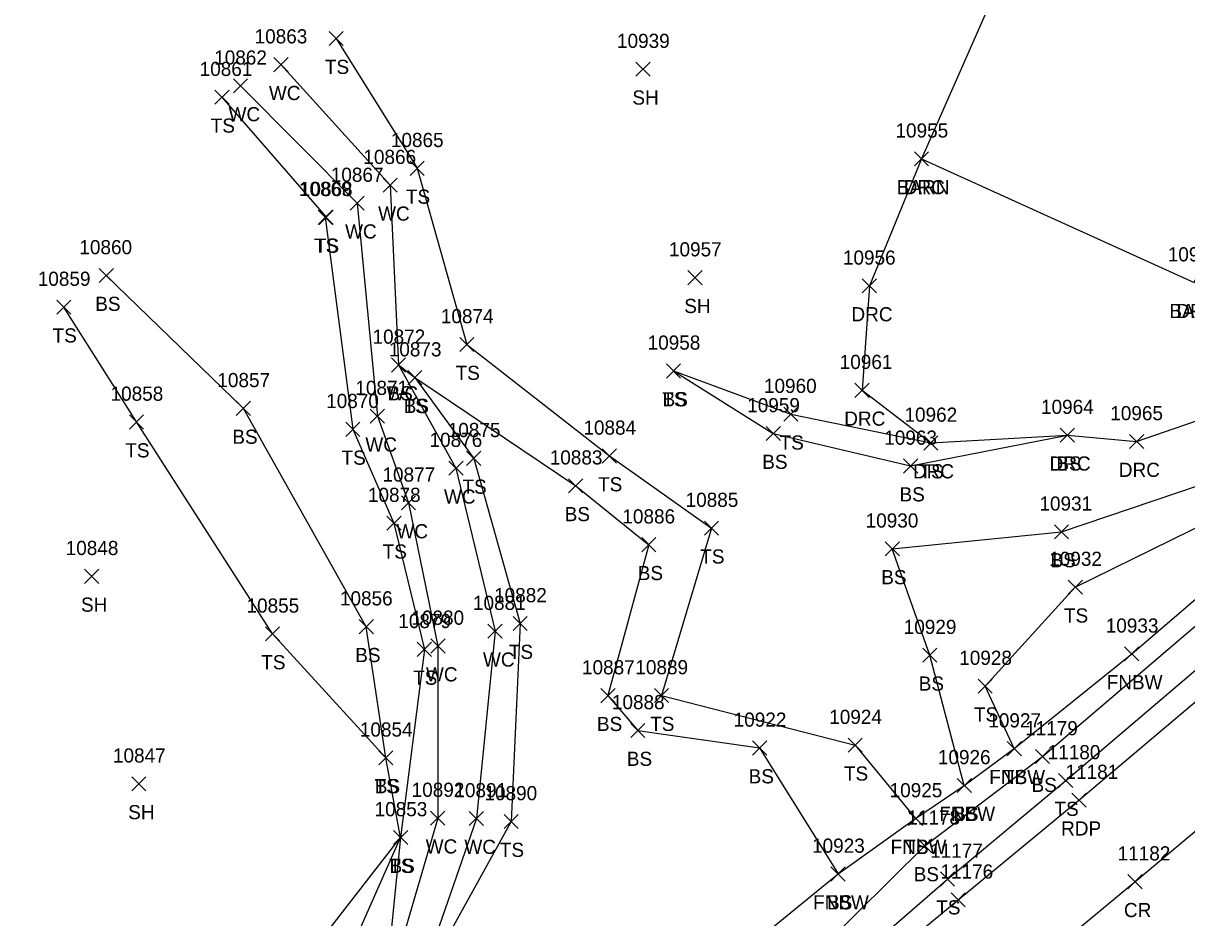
# Model space of a CAD drawing. Extents: x 1475671 to 1477951, y 592661 to 593821.
# Drawn here: x 1476576.7 to 1476740.9, y 593233.2 to 593359.5 of the extents above; entities that cross this region are included whole.
import ezdxf

# ---------------------------------------------------------------- set-up
doc = ezdxf.new("R2010")
doc.units = 0
for name, color, linetype in [('L_A', 7, 'Continuous'), ('L_I', 7, 'Continuous'), ('L_TIC', 7, 'Continuous'), ('LAWE', 7, 'Continuous'), ('LBC', 7, 'Continuous'), ('LELB', 7, 'Continuous'), ('LFNC', 7, 'Continuous'), ('P_A', 7, 'Continuous'), ('P_I', 7, 'Continuous'), ('P_TIC', 7, 'Continuous'), ('PET', 7, 'Continuous'), ('PRC', 7, 'Continuous'), ('R_A', 7, 'Continuous'), ('R_I', 7, 'Continuous'), ('R_TIC', 7, 'Continuous'), ('RDP', 7, 'Continuous')]:
    doc.layers.add(name, color=color, linetype=linetype)

msp = doc.modelspace()

# ---------------------------------------------------------------- linework, layer by layer
at = {"layer": 'L_TIC'}
for points in [[(1476619.88, 593356.33), (1476621.88, 593358.33)], [(1476621.88, 593356.33), (1476619.88, 593358.33)], [(1476612.09, 593352.64), (1476614.09, 593354.64)], [(1476614.09, 593352.64), (1476612.09, 593354.64)], [(1476663.18, 593352), (1476665.18, 593354)], [(1476665.18, 593352), (1476663.18, 593354)], [(1476606.39, 593349.65), (1476608.39, 593351.65)], [(1476608.39, 593349.65), (1476606.39, 593351.65)], [(1476603.77, 593348.04), (1476605.77, 593350.04)], [(1476605.77, 593348.04), (1476603.77, 593350.04)], [(1476631.31, 593338.01), (1476633.31, 593340.01)], [(1476633.31, 593338.01), (1476631.31, 593340.01)], [(1476702.46, 593339.35), (1476704.46, 593341.35)], [(1476704.46, 593339.35), (1476702.46, 593341.35)], [(1476627.49, 593335.62), (1476629.49, 593337.62)], [(1476629.49, 593335.62), (1476627.49, 593337.62)], [(1476622.84, 593333.1), (1476624.84, 593335.1)], [(1476624.84, 593333.1), (1476622.84, 593335.1)], [(1476618.35, 593331.1), (1476620.35, 593333.1)], [(1476620.35, 593331.1), (1476618.35, 593333.1)], [(1476618.47, 593331.09), (1476620.47, 593333.09)], [(1476620.47, 593331.09), (1476618.47, 593333.09)], [(1476587.45, 593322.88), (1476589.45, 593324.88)], [(1476589.45, 593322.88), (1476587.45, 593324.88)], [(1476670.5, 593322.58), (1476672.5, 593324.58)], [(1476672.5, 593322.58), (1476670.5, 593324.58)], [(1476581.46, 593318.42), (1476583.46, 593320.42)], [(1476583.46, 593318.42), (1476581.46, 593320.42)], [(1476638.32, 593313.14), (1476640.32, 593315.14)], [(1476640.32, 593313.14), (1476638.32, 593315.14)], [(1476628.68, 593310.25), (1476630.68, 593312.25)], [(1476630.68, 593310.25), (1476628.68, 593312.25)], [(1476628.68, 593310.25), (1476630.68, 593312.25)], [(1476630.68, 593310.25), (1476628.68, 593312.25)], [(1476630.97, 593308.46), (1476632.97, 593310.46)], [(1476632.97, 593308.46), (1476630.97, 593310.46)], [(1476630.97, 593308.46), (1476632.97, 593310.46)], [(1476632.97, 593308.46), (1476630.97, 593310.46)], [(1476667.48, 593309.41), (1476669.48, 593311.41)], [(1476669.48, 593309.41), (1476667.48, 593311.41)], [(1476667.48, 593309.41), (1476669.48, 593311.41)], [(1476669.48, 593309.41), (1476667.48, 593311.41)], [(1476606.79, 593304.12), (1476608.79, 593306.12)], [(1476608.79, 593304.12), (1476606.79, 593306.12)], [(1476591.72, 593302.2), (1476593.72, 593304.2)], [(1476593.72, 593302.2), (1476591.72, 593304.2)], [(1476625.69, 593303.02), (1476627.69, 593305.02)], [(1476627.69, 593303.02), (1476625.69, 593305.02)], [(1476684.03, 593303.3), (1476686.03, 593305.3)], [(1476686.03, 593303.3), (1476684.03, 593305.3)], [(1476622.23, 593301.17), (1476624.23, 593303.17)], [(1476624.23, 593301.17), (1476622.23, 593303.17)], [(1476681.55, 593300.58), (1476683.55, 593302.58)], [(1476683.55, 593300.58), (1476681.55, 593302.58)], [(1476723.04, 593300.34), (1476725.04, 593302.34)], [(1476725.04, 593300.34), (1476723.04, 593302.34)], [(1476703.77, 593299.24), (1476705.77, 593301.24)], [(1476705.77, 593299.24), (1476703.77, 593301.24)], [(1476639.29, 593297.07), (1476641.29, 593299.07)], [(1476641.29, 593297.07), (1476639.29, 593299.07)], [(1476658.42, 593297.41), (1476660.42, 593299.41)], [(1476660.42, 593297.41), (1476658.42, 593299.41)], [(1476636.78, 593295.68), (1476638.78, 593297.68)], [(1476638.78, 593295.68), (1476636.78, 593297.68)], [(1476700.92, 593295.99), (1476702.92, 593297.99)], [(1476702.92, 593295.99), (1476700.92, 593297.99)], [(1476653.68, 593293.2), (1476655.68, 593295.2)], [(1476655.68, 593293.2), (1476653.68, 593295.2)], [(1476630.08, 593290.78), (1476632.08, 593292.78)], [(1476632.08, 593290.78), (1476630.08, 593292.78)], [(1476628.03, 593287.92), (1476630.03, 593289.92)], [(1476630.03, 593287.92), (1476628.03, 593289.92)], [(1476672.84, 593287.22), (1476674.84, 593289.22)], [(1476674.84, 593287.22), (1476672.84, 593289.22)], [(1476722.21, 593286.69), (1476724.21, 593288.69)], [(1476724.21, 593286.69), (1476722.21, 593288.69)], [(1476663.99, 593284.88), (1476665.99, 593286.88)], [(1476665.99, 593284.88), (1476663.99, 593286.88)], [(1476698.34, 593284.3), (1476700.34, 593286.3)], [(1476700.34, 593284.3), (1476698.34, 593286.3)], [(1476585.39, 593280.42), (1476587.39, 593282.42)], [(1476587.39, 593280.42), (1476585.39, 593282.42)], [(1476724.15, 593278.89), (1476726.15, 593280.89)], [(1476726.15, 593278.89), (1476724.15, 593280.89)], [(1476645.83, 593273.76), (1476647.83, 593275.76)], [(1476647.83, 593273.76), (1476645.83, 593275.76)], [(1476610.9, 593272.29), (1476612.9, 593274.29)], [(1476612.9, 593272.29), (1476610.9, 593274.29)], [(1476624.13, 593273.31), (1476626.13, 593275.31)], [(1476626.13, 593273.31), (1476624.13, 593275.31)], [(1476642.29, 593272.67), (1476644.29, 593274.67)], [(1476644.29, 593272.67), (1476642.29, 593274.67)], [(1476634.24, 593270.58), (1476636.24, 593272.58)], [(1476636.24, 593270.58), (1476634.24, 593272.58)], [(1476632.33, 593270.11), (1476634.33, 593272.11)], [(1476634.33, 593270.11), (1476632.33, 593272.11)], [(1476703.63, 593269.28), (1476705.63, 593271.28)], [(1476705.63, 593269.28), (1476703.63, 593271.28)], [(1476732.12, 593269.47), (1476734.12, 593271.47)], [(1476734.12, 593269.47), (1476732.12, 593271.47)], [(1476711.45, 593264.92), (1476713.45, 593266.92)], [(1476713.45, 593264.92), (1476711.45, 593266.92)], [(1476658.23, 593263.58), (1476660.23, 593265.58)], [(1476660.23, 593263.58), (1476658.23, 593265.58)], [(1476665.77, 593263.59), (1476667.77, 593265.59)], [(1476667.77, 593263.59), (1476665.77, 593265.59)], [(1476662.45, 593258.66), (1476664.45, 593260.66)], [(1476664.45, 593258.66), (1476662.45, 593260.66)], [(1476679.62, 593256.19), (1476681.62, 593258.19)], [(1476681.62, 593256.19), (1476679.62, 593258.19)], [(1476693.11, 593256.58), (1476695.11, 593258.58)], [(1476695.11, 593256.58), (1476693.11, 593258.58)], [(1476715.55, 593256.09), (1476717.55, 593258.09)], [(1476717.55, 593256.09), (1476715.55, 593258.09)], [(1476715.55, 593256.09), (1476717.55, 593258.09)], [(1476717.55, 593256.09), (1476715.55, 593258.09)], [(1476626.89, 593254.79), (1476628.89, 593256.79)], [(1476628.89, 593254.79), (1476626.89, 593256.79)], [(1476626.89, 593254.79), (1476628.89, 593256.79)], [(1476628.89, 593254.79), (1476626.89, 593256.79)], [(1476719.54, 593254.98), (1476721.54, 593256.98)], [(1476721.54, 593254.98), (1476719.54, 593256.98)], [(1476592.05, 593251.13), (1476594.05, 593253.13)], [(1476594.05, 593251.13), (1476592.05, 593253.13)], [(1476708.5, 593250.9), (1476710.5, 593252.9)], [(1476710.5, 593250.9), (1476708.5, 593252.9)], [(1476708.5, 593250.9), (1476710.5, 593252.9)], [(1476710.5, 593250.9), (1476708.5, 593252.9)], [(1476722.81, 593251.6), (1476724.81, 593253.6)], [(1476724.81, 593251.6), (1476722.81, 593253.6)], [(1476634.2, 593246.29), (1476636.2, 593248.29)], [(1476636.2, 593246.29), (1476634.2, 593248.29)], [(1476639.66, 593246.23), (1476641.66, 593248.23)], [(1476641.66, 593246.23), (1476639.66, 593248.23)], [(1476701.63, 593246.23), (1476703.63, 593248.23)], [(1476703.63, 593246.23), (1476701.63, 593248.23)], [(1476701.63, 593246.23), (1476703.63, 593248.23)], [(1476703.63, 593246.23), (1476701.63, 593248.23)], [(1476644.56, 593245.81), (1476646.56, 593247.81)], [(1476646.56, 593245.81), (1476644.56, 593247.81)], [(1476628.97, 593243.55), (1476630.97, 593245.55)], [(1476630.97, 593243.55), (1476628.97, 593245.55)], [(1476628.97, 593243.55), (1476630.97, 593245.55)], [(1476630.97, 593243.55), (1476628.97, 593245.55)], [(1476628.97, 593243.55), (1476630.97, 593245.55)], [(1476630.97, 593243.55), (1476628.97, 593245.55)], [(1476702.92, 593242.37), (1476704.92, 593244.37)], [(1476704.92, 593242.37), (1476702.92, 593244.37)], [(1476690.69, 593238.4), (1476692.69, 593240.4)], [(1476692.69, 593238.4), (1476690.69, 593240.4)], [(1476690.69, 593238.4), (1476692.69, 593240.4)], [(1476692.69, 593238.4), (1476690.69, 593240.4)], [(1476706.13, 593237.69), (1476708.13, 593239.69)], [(1476708.13, 593237.69), (1476706.13, 593239.69)]]:
    msp.add_lwpolyline(points, dxfattribs=at)
at = {"layer": 'LAWE'}
for points in [[(1476613.09, 593353.64), (1476628.49, 593336.62), (1476629.68, 593311.25), (1476637.78, 593296.68), (1476643.29, 593273.67), (1476640.66, 593247.23), (1476633.78, 593227.3), (1476632.16, 593210.64), (1476623.48, 593192.05), (1476621.73, 593187.97), (1476618.95, 593180.66)], [(1476607.39, 593350.65), (1476623.84, 593334.1), (1476626.69, 593304.02), (1476631.08, 593291.78), (1476635.24, 593271.58), (1476635.2, 593247.29), (1476629.57, 593228.01), (1476628.52, 593211.44), (1476620.49, 593193.84), (1476617.53, 593189.7), (1476607.49, 593183.62), (1476609.32, 593177.24), (1476612.65, 593176.23), (1476614.24, 593174.55), (1476618.55, 593176.15), (1476618.95, 593180.66)]]:
    msp.add_lwpolyline(points, dxfattribs=at)
at = {"layer": 'LBC'}
msp.add_lwpolyline([(1476766.99, 593478.72), (1476749.47, 593442.92), (1476737.05, 593415.38), (1476717.88, 593373.12), (1476703.46, 593340.35), (1476741.92, 593322.87), (1476753.1, 593346.5), (1476762.35, 593367.35), (1476787.68, 593423.01), (1476791.87, 593432.58)], dxfattribs=at)
at = {"layer": 'LELB'}
for points in [[(1476660.79, 593199.46), (1476674.63, 593214.33), (1476703.92, 593243.37), (1476720.54, 593255.98), (1476751.7, 593282.61), (1476781.77, 593307.79), (1476789.04, 593316.89), (1476807.89, 593333.24), (1476839.71, 593357.28), (1476859.97, 593374.46), (1476882.16, 593391.96), (1476882.87, 593395.08), (1476884.75, 593398.78), (1476886.94, 593401.06), (1476880.92, 593405.09), (1476872.21, 593402.61), (1476869.35, 593406.91), (1476883.46, 593416.6), (1476894.87, 593423.54), (1476922.16, 593439.01), (1476941.74, 593451.3), (1476958.3, 593465.19), (1476973.77, 593478.9)], [(1476525.71, 593116.6), (1476535.99, 593117.47), (1476564.39, 593135.96), (1476604.97, 593161.16), (1476624.83, 593173.86), (1476638.09, 593183.34), (1476660.79, 593199.46), (1476676.81, 593212.32), (1476707.13, 593238.69), (1476723.81, 593252.6), (1476754.14, 593278.44), (1476785.31, 593303.01), (1476812.8, 593326.19), (1476842.99, 593352.59), (1476863.07, 593369.43), (1476886.56, 593389.77), (1476893.66, 593396.85), (1476901.2, 593401.68), (1476921.17, 593422.2)], [(1476709.5, 593251.9), (1476704.63, 593270.28), (1476699.34, 593285.3), (1476723.21, 593287.69), (1476755.77, 593298.72), (1476777.04, 593314.27), (1476785.1, 593323.82), (1476803.07, 593341.35), (1476835.49, 593361.82), (1476853.06, 593384.39), (1476874.85, 593397.11), (1476884.75, 593398.78)], [(1476716.55, 593257.09), (1476712.45, 593265.92), (1476725.15, 593279.89), (1476757.78, 593295.95), (1476779.66, 593309.61), (1476787.04, 593319.52), (1476805.64, 593337.64), (1476837.49, 593359.29), (1476857.09, 593379.03), (1476877.34, 593393.41), (1476882.87, 593395.08)], [(1476620.88, 593357.33), (1476632.31, 593339.01), (1476639.32, 593314.14), (1476659.42, 593298.41), (1476673.84, 593288.22), (1476666.77, 593264.59), (1476694.11, 593257.58), (1476702.63, 593247.23)], [(1476604.77, 593349.04), (1476619.47, 593332.09), (1476619.35, 593332.1), (1476623.23, 593302.17), (1476629.03, 593288.92), (1476633.33, 593271.11)], [(1476627.89, 593255.79), (1476625.13, 593274.31), (1476607.79, 593305.12), (1476588.45, 593323.88)], [(1476629.97, 593244.55), (1476627.89, 593255.79), (1476611.9, 593273.29), (1476592.72, 593303.2), (1476582.46, 593319.42)], [(1476629.68, 593311.25), (1476631.97, 593309.46), (1476654.68, 593294.2), (1476664.99, 593285.88), (1476659.23, 593264.58), (1476663.45, 593259.66), (1476680.62, 593257.19), (1476691.69, 593239.4)], [(1476668.48, 593310.41), (1476685.03, 593304.3), (1476704.77, 593300.24)], [(1476668.48, 593310.41), (1476682.55, 593301.58), (1476701.92, 593296.99), (1476724.04, 593301.34)], [(1476631.97, 593309.46), (1476640.29, 593298.07), (1476646.83, 593274.76), (1476645.56, 593246.81), (1476635.23, 593228.07), (1476634.06, 593210.85), (1476624.18, 593191.42), (1476621.73, 593187.97), (1476617.53, 593189.7)], [(1476633.33, 593271.11), (1476629.97, 593244.55)], [(1476600.34, 593167.51), (1476594.26, 593178.25), (1476596.2, 593189.62), (1476609.35, 593213.75), (1476616.22, 593226.87), (1476629.97, 593244.55), (1476628.33, 593228.14), (1476627.49, 593211.59), (1476619.26, 593195.1), (1476617.53, 593189.7)], [(1476602.47, 593173.82), (1476600.14, 593185.69), (1476613.85, 593211.55), (1476621.5, 593225.4), (1476629.97, 593244.55)]]:
    msp.add_lwpolyline(points, dxfattribs=at)
at = {"layer": 'LFNC'}
msp.add_lwpolyline([(1476458.99, 593083.01), (1476499.73, 593099.84), (1476506.4, 593103.47), (1476506.74, 593103.7), (1476516.66, 593109.69), (1476525.71, 593116.6), (1476534.13, 593120.72), (1476545.43, 593126.64), (1476563.76, 593138.28), (1476600.34, 593167.51), (1476610.45, 593174.4), (1476612.65, 593176.23), (1476618.95, 593180.66), (1476640, 593195.61), (1476653.4, 593207.77), (1476664.49, 593217.17), (1476691.69, 593239.4), (1476702.63, 593247.23), (1476709.5, 593251.9), (1476716.55, 593257.09), (1476733.12, 593270.47), (1476759.81, 593293.37)], dxfattribs=at)
at = {"layer": 'P_TIC'}
for points in [[(1476724.67, 593248.83), (1476726.67, 593250.83)], [(1476726.67, 593248.83), (1476724.67, 593250.83)], [(1476732.58, 593237.31), (1476734.58, 593239.31)], [(1476734.58, 593237.31), (1476732.58, 593239.31)], [(1476707.64, 593234.75), (1476709.64, 593236.75)], [(1476709.64, 593234.75), (1476707.64, 593236.75)]]:
    msp.add_lwpolyline(points, dxfattribs=at)
at = {"layer": 'PET'}
msp.add_lwpolyline([(1476459.25, 593078.48), (1476508.39, 593100.17), (1476518.15, 593105.13), (1476565.38, 593131.07), (1476607.43, 593157.45), (1476640.25, 593180.54), (1476678.21, 593210.57), (1476708.64, 593235.75), (1476725.67, 593249.83), (1476755.84, 593275.3), (1476786.3, 593300.73), (1476814.32, 593324.28), (1476845.05, 593350.02), (1476865.02, 593366.82), (1476897.04, 593395.14), (1476922.98, 593419.08), (1476952.36, 593443.37)], dxfattribs=at)
at = {"layer": 'PRC'}
msp.add_lwpolyline([(1476461.98, 593064.62), (1476520.7, 593090.52), (1476540.79, 593101.34), (1476577.67, 593121.61), (1476614.51, 593145.69), (1476649.36, 593170.81), (1476687.02, 593200.01), (1476716.69, 593224.25), (1476733.58, 593238.31), (1476760.9, 593261.21), (1476795.35, 593290.14), (1476823.06, 593313.51), (1476854.07, 593339.52), (1476875.7, 593357.51), (1476907.01, 593384.08), (1476934.06, 593407.68), (1476963.46, 593432.81)], dxfattribs=at)
at = {"layer": 'R_TIC'}
for points in [[(1476702.46, 593339.35), (1476704.46, 593341.35)], [(1476704.46, 593339.35), (1476702.46, 593341.35)], [(1476695.1, 593321.41), (1476697.1, 593323.41)], [(1476697.1, 593321.41), (1476695.1, 593323.41)], [(1476694.07, 593306.68), (1476696.07, 593308.68)], [(1476696.07, 593306.68), (1476694.07, 593308.68)], [(1476723.04, 593300.34), (1476725.04, 593302.34)], [(1476725.04, 593300.34), (1476723.04, 593302.34)], [(1476703.77, 593299.24), (1476705.77, 593301.24)], [(1476705.77, 593299.24), (1476703.77, 593301.24)], [(1476732.81, 593299.45), (1476734.81, 593301.45)], [(1476734.81, 593299.45), (1476732.81, 593301.45)]]:
    msp.add_lwpolyline(points, dxfattribs=at)
at = {"layer": 'RDP'}
msp.add_lwpolyline([(1476703.46, 593340.35), (1476696.1, 593322.41), (1476695.07, 593307.68), (1476704.77, 593300.24), (1476724.04, 593301.34), (1476733.81, 593300.45), (1476747.14, 593305.07), (1476767.96, 593315.71), (1476784.22, 593330.11), (1476798.42, 593350.68), (1476808.5, 593366.53)], dxfattribs=at)

# ---------------------------------------------------------------- texts
at = {"layer": 'L_A'}
for s, p in [('TS', (1476619.29, 593352.33)), ('WC', (1476611.39, 593348.64)), ('SH', (1476662.67, 593348)), ('WC', (1476605.7, 593345.65)), ('TS', (1476603.18, 593344.04)), ('BARN', (1476699.97, 593335.35)), ('TS', (1476630.72, 593334.01)), ('WC', (1476626.8, 593331.62)), ('WC', (1476622.14, 593329.1)), ('TS', (1476617.76, 593327.1)), ('TS', (1476617.88, 593327.09)), ('BS', (1476586.89, 593318.88)), ('SH', (1476669.99, 593318.58)), ('BARN', (1476738.43, 593317.87)), ('TS', (1476580.87, 593314.42)), ('TS', (1476637.73, 593309.14)), ('WC', (1476627.99, 593306.25)), ('BS', (1476628.12, 593306.25)), ('TS', (1476666.89, 593305.41)), ('BS', (1476666.93, 593305.41)), ('TS', (1476630.38, 593304.46)), ('BS', (1476630.41, 593304.46)), ('BS', (1476606.23, 593300.12)), ('WC', (1476625, 593299.02)), ('TS', (1476683.44, 593299.3)), ('TS', (1476591.13, 593298.2)), ('TS', (1476621.64, 593297.17)), ('BS', (1476680.99, 593296.58)), ('TS', (1476703.18, 593295.24)), ('BS', (1476722.48, 593296.34)), ('TS', (1476638.7, 593293.07)), ('TS', (1476657.83, 593293.41)), ('BS', (1476700.36, 593291.99)), ('WC', (1476636.09, 593291.68)), ('BS', (1476653.12, 593289.2)), ('WC', (1476629.39, 593286.78)), ('TS', (1476627.44, 593283.92)), ('TS', (1476672.25, 593283.22)), ('BS', (1476721.65, 593282.69)), ('BS', (1476663.43, 593280.88)), ('BS', (1476697.78, 593280.3)), ('SH', (1476584.88, 593276.42)), ('TS', (1476723.56, 593274.89)), ('BS', (1476623.57, 593269.31)), ('TS', (1476645.24, 593269.76)), ('TS', (1476610.31, 593268.29)), ('WC', (1476641.59, 593268.67)), ('TS', (1476631.74, 593266.11)), ('WC', (1476633.55, 593266.58)), ('BS', (1476703.07, 593265.28)), ('FNBW', (1476729.59, 593265.47)), ('TS', (1476710.86, 593260.92)), ('BS', (1476657.67, 593259.58)), ('TS', (1476665.18, 593259.59)), ('BS', (1476661.89, 593254.66)), ('TS', (1476692.52, 593252.58)), ('TS', (1476626.3, 593250.79)), ('BS', (1476626.33, 593250.79)), ('BS', (1476679.07, 593252.19)), ('FNBW', (1476713.02, 593252.09)), ('TS', (1476714.96, 593252.09)), ('BS', (1476718.98, 593250.98)), ('TS', (1476722.22, 593247.6)), ('SH', (1476591.54, 593247.13)), ('FNBW', (1476705.97, 593246.9)), ('BS', (1476707.94, 593246.9)), ('WC', (1476633.51, 593242.29)), ('WC', (1476638.97, 593242.23)), ('TS', (1476643.97, 593241.81)), ('FNBW', (1476699.1, 593242.23)), ('TS', (1476701.04, 593242.23)), ('TS', (1476628.38, 593239.55)), ('TS', (1476628.38, 593239.55)), ('BS', (1476628.41, 593239.55)), ('BS', (1476702.36, 593238.37)), ('FNBW', (1476688.16, 593234.4)), ('BS', (1476690.13, 593234.4)), ('TS', (1476705.54, 593233.69))]:
    msp.add_text(s, height=2, dxfattribs=at).set_placement(p)
at = {"layer": 'L_I'}
for s, p in [('10863', (1476609.37, 593356.64)), ('10939', (1476660.5, 593356)), ('10862', (1476603.67, 593353.65)), ('10861', (1476601.62, 593352.04)), ('10955', (1476699.79, 593343.35)), ('10865', (1476628.6, 593342.01)), ('10866', (1476624.72, 593339.62)), ('10867', (1476620.12, 593337.1)), ('10869', (1476615.63, 593335.1)), ('10868', (1476615.76, 593335.09)), ('10860', (1476584.65, 593326.88)), ('10957', (1476667.83, 593326.58)), ('10967', (1476738.2, 593325.87)), ('10859', (1476578.78, 593322.42)), ('10874', (1476635.65, 593317.14)), ('10872', (1476626.01, 593314.25)), ('10872', (1476626.01, 593314.25)), ('10958', (1476664.82, 593313.41)), ('10958', (1476664.82, 593313.41)), ('10873', (1476628.3, 593312.46)), ('10873', (1476628.3, 593312.46)), ('10857', (1476604.12, 593308.12)), ('10871', (1476623.59, 593307.02)), ('10960', (1476681.23, 593307.3)), ('10858', (1476589.05, 593306.2)), ('10870', (1476619.47, 593305.17)), ('10959', (1476678.87, 593304.58)), ('10964', (1476720.32, 593304.34)), ('10962', (1476701.06, 593303.24)), ('10875', (1476636.62, 593301.07)), ('10884', (1476655.76, 593301.41)), ('10876', (1476634.05, 593299.68)), ('10963', (1476698.2, 593299.99)), ('10883', (1476651.01, 593297.2)), ('10877', (1476627.41, 593294.78)), ('10878', (1476625.36, 593291.92)), ('10885', (1476670.18, 593291.22)), ('10931', (1476720.1, 593290.69)), ('10886', (1476661.26, 593288.88)), ('10930', (1476695.58, 593288.3)), ('10848', (1476582.72, 593284.42)), ('10932', (1476721.48, 593282.89)), ('10856', (1476621.41, 593277.31)), ('10882', (1476643.16, 593277.76)), ('10855', (1476608.23, 593276.29)), ('10881', (1476640.18, 593276.67)), ('10879', (1476629.65, 593274.11)), ('10880', (1476631.49, 593274.58)), ('10929', (1476700.95, 593273.28)), ('10933', (1476729.45, 593273.47)), ('10928', (1476708.78, 593268.92)), ('10887', (1476655.56, 593267.58)), ('10889', (1476663.09, 593267.59)), ('10888', (1476659.78, 593262.66)), ('10922', (1476676.96, 593260.19)), ('10924', (1476690.44, 593260.58)), ('10927', (1476712.88, 593260.09)), ('10927', (1476712.88, 593260.09)), ('11179', (1476718.08, 593258.98)), ('10854', (1476624.22, 593258.79)), ('10854', (1476624.22, 593258.79)), ('10847', (1476589.39, 593255.13)), ('10926', (1476705.77, 593254.9)), ('10926', (1476705.77, 593254.9)), ('11180', (1476721.26, 593255.6)), ('10892', (1476631.53, 593250.29)), ('10891', (1476637.56, 593250.23)), ('10890', (1476641.8, 593249.81)), ('10925', (1476698.96, 593250.23)), ('10925', (1476698.96, 593250.23)), ('10853', (1476626.3, 593247.55)), ('10853', (1476626.3, 593247.55)), ('10853', (1476626.3, 593247.55)), ('11178', (1476701.46, 593246.37)), ('10923', (1476688.02, 593242.4)), ('10923', (1476688.02, 593242.4)), ('11177', (1476704.67, 593241.69))]:
    msp.add_text(s, height=2, dxfattribs=at).set_placement(p)
at = {"layer": 'P_A'}
for s, p in [('RDP', (1476723.16, 593244.83)), ('CR', (1476732.02, 593233.31))]:
    msp.add_text(s, height=2, dxfattribs=at).set_placement(p)
at = {"layer": 'P_I'}
for s, p in [('11181', (1476723.78, 593252.83)), ('11182', (1476731.13, 593241.31)), ('11176', (1476706.13, 593238.75))]:
    msp.add_text(s, height=2, dxfattribs=at).set_placement(p)
at = {"layer": 'R_A'}
for p in [(1476700.95, 593335.35), (1476693.58, 593317.41), (1476739.41, 593317.87), (1476692.56, 593302.68), (1476702.26, 593295.24), (1476721.53, 593296.34), (1476731.3, 593295.45)]:
    msp.add_text('DRC', height=2, dxfattribs=at).set_placement(p)
at = {"layer": 'R_I'}
for s, p in [('10955', (1476699.79, 593343.35)), ('10956', (1476692.37, 593325.41)), ('10967', (1476738.2, 593325.87)), ('10961', (1476691.92, 593310.68)), ('10964', (1476720.32, 593304.34)), ('10965', (1476730.09, 593303.45)), ('10962', (1476701.06, 593303.24))]:
    msp.add_text(s, height=2, dxfattribs=at).set_placement(p)

doc.saveas('drawing.dxf')
